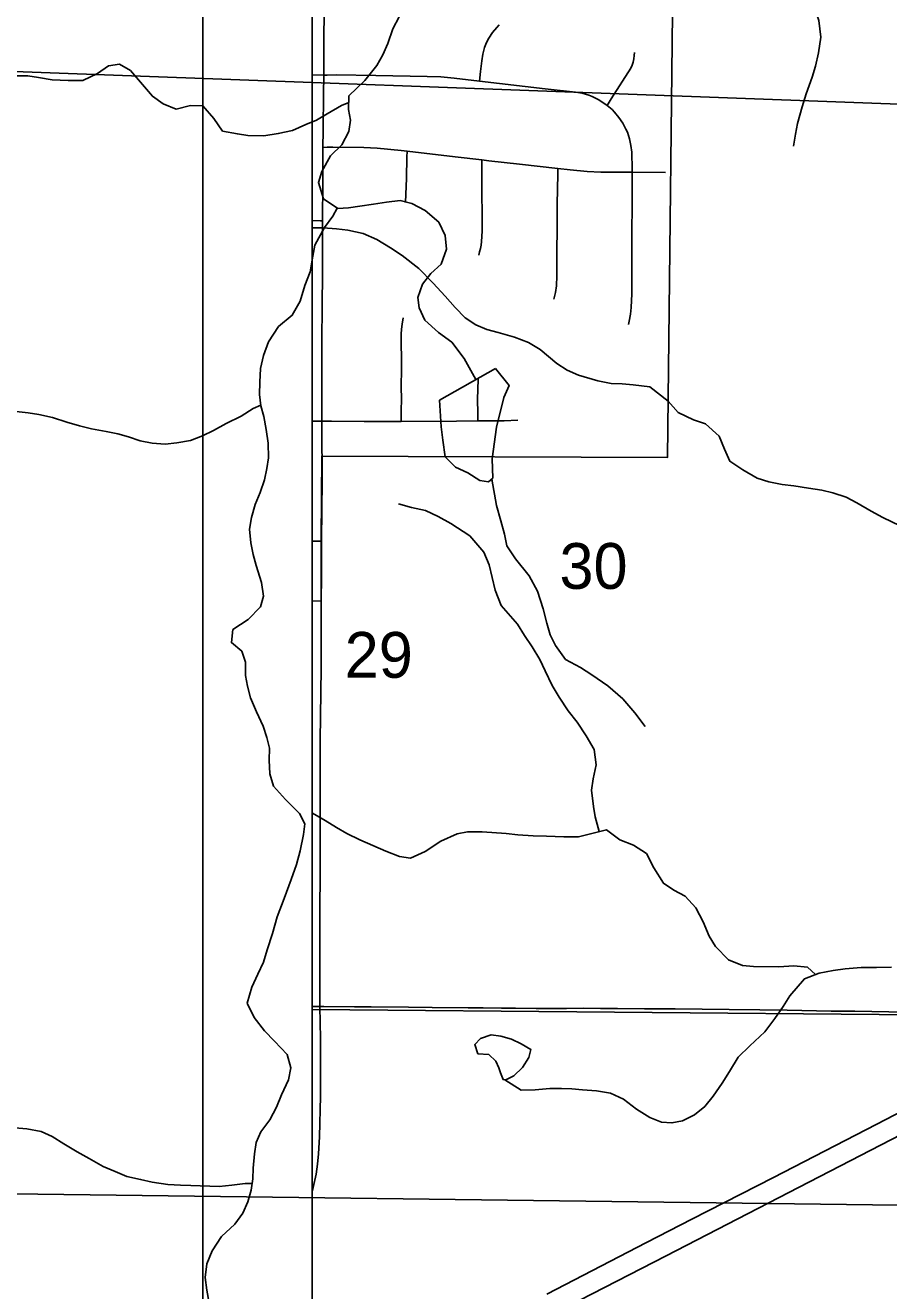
# Model space of a CAD drawing. Extents: x 0 to 34, y 0 to 22.
# Drawn here: x 12.978 to 13.767, y 14.964 to 16.121 of the extents above; entities that cross this region are included whole.
import ezdxf

# ---------------------------------------------------------------- set-up
doc = ezdxf.new("R2010")
doc.units = 0
for name, color, linetype in [('GM_X_City_Street', 7, 'Continuous'), ('GM_X_Corporation', 7, 'Continuous'), ('GM_X_County_Road', 7, 'Continuous'), ('GM_X_Interstate_Route', 7, 'Continuous'), ('GM_X_Minor_Lake', 7, 'Continuous'), ('GM_X_Minor_River', 7, 'Continuous'), ('GM_X_Rail_Line', 7, 'Continuous'), ('GM_X_Section', 7, 'Continuous'), ('GM_X_Section_Text', 7, 'Continuous'), ('GM_X_US_Shield', 7, 'Continuous'), ('SH_Data', 7, 'Continuous')]:
    doc.layers.add(name, color=color, linetype=linetype)

msp = doc.modelspace()

# ---------------------------------------------------------------- linework, layer by layer
at = {"layer": 'GM_X_City_Street'}
for p, q in [((13.2404, 16.0756), (13.2509, 16.0753)), ((13.2404, 15.7589), (13.2491, 15.759)), ((13.2404, 15.6492), (13.2489, 15.6491))]:
    msp.add_line(p, q, dxfattribs=at)
for points in [[(13.3933, 16.0698), (13.3943, 16.0785), (13.3955, 16.0884), (13.3965, 16.0945), (13.398, 16.1006), (13.399, 16.1035), (13.4002, 16.1063), (13.4017, 16.1091), (13.4052, 16.1142), (13.4092, 16.119), (13.4114, 16.1212)], [(13.51, 16.0476), (13.5138, 16.0536), (13.5315, 16.0816), (13.5328, 16.0844), (13.5338, 16.0871), (13.5344, 16.0901), (13.5347, 16.0931), (13.5349, 16.0961)], [(13.2509, 16.0753), (13.2542, 16.0754), (13.2624, 16.0755), (13.2986, 16.0749), (13.3455, 16.0741), (13.3579, 16.0736), (13.3703, 16.0724), (13.3933, 16.0698), (13.4533, 16.0629), (13.481, 16.0598), (13.4872, 16.0587), (13.4932, 16.0569), (13.4962, 16.0558), (13.5018, 16.0529), (13.5071, 16.0497), (13.51, 16.0476), (13.5145, 16.0438), (13.5167, 16.0415), (13.5207, 16.0367), (13.5242, 16.0315), (13.5272, 16.0259), (13.5285, 16.0231), (13.5296, 16.0201), (13.5305, 16.0171), (13.5317, 16.011), (13.5324, 16.0047), (13.5327, 15.9889), (13.5327, 15.9867)], [(13.2502, 16.0092), (13.2542, 16.0093), (13.2594, 16.0093), (13.2875, 16.009), (13.2999, 16.0084), (13.3216, 16.0064), (13.3271, 16.0058), (13.3711, 16.0005), (13.3954, 15.9977), (13.4018, 15.997), (13.4299, 15.9939), (13.4649, 15.9899), (13.4763, 15.9886), (13.4918, 15.9872), (13.5042, 15.9867), (13.5327, 15.9867), (13.5634, 15.9863)], [(13.3258, 15.9587), (13.3267, 15.9811), (13.327, 16.0002), (13.3271, 16.0058)], [(13.3926, 15.9108), (13.3934, 15.9137), (13.3942, 15.9169), (13.3948, 15.9199), (13.3951, 15.9231), (13.3956, 15.9325), (13.3954, 15.9827), (13.3954, 15.9922), (13.3954, 15.9977)], [(13.4614, 15.8703), (13.4628, 15.8764), (13.4636, 15.8826), (13.4641, 15.8919), (13.4643, 15.9573), (13.4648, 15.9847), (13.4649, 15.9899)], [(13.5294, 15.8473), (13.5302, 15.8504), (13.5312, 15.8566), (13.5318, 15.8628), (13.5324, 15.8753), (13.5325, 15.8878), (13.5325, 15.9159), (13.5325, 15.9283), (13.5325, 15.9377), (13.5327, 15.9501), (13.5328, 15.9626), (13.5327, 15.9867)], [(13.2404, 15.9423), (13.2481, 15.9422), (13.2498, 15.9422)], [(13.3218, 15.7586), (13.3218, 15.7647), (13.3218, 15.7677), (13.3219, 15.78), (13.3218, 15.7892), (13.322, 15.8076), (13.3218, 15.8383), (13.322, 15.8429), (13.3226, 15.8475), (13.3237, 15.8535)], [(13.3918, 15.7592), (13.3917, 15.7662), (13.3915, 15.7787), (13.392, 15.7974)], [(13.2491, 15.759), (13.2581, 15.7589), (13.2878, 15.7587), (13.3218, 15.7586), (13.3722, 15.759), (13.3918, 15.7592), (13.3972, 15.7592), (13.416, 15.7592), (13.4285, 15.7597)]]:
    msp.add_lwpolyline(points, dxfattribs=at)
at = {"layer": 'GM_X_Corporation'}
msp.add_lwpolyline([(13.2404, 19.7446), (13.2404, 15.5945), (13.2485, 15.5944), (13.2487, 15.6513), (13.2492, 15.7269), (13.565, 15.7255), (13.5708, 16.2404), (13.5808, 16.7296), (14.5791, 16.7149), (14.5699, 16.2993), (14.5699, 16.2941), (14.627, 16.2968)], dxfattribs=at)
at = {"layer": 'GM_X_County_Road'}
msp.add_line((13.2404, 15.2236), (13.2475, 15.2236), dxfattribs=at)
for points in [[(13.2509, 16.0753), (13.251, 16.1085), (13.2512, 16.1326), (13.2512, 16.1457), (13.251, 16.1612), (13.2513, 16.1885), (13.2516, 16.211), (13.2518, 16.2247), (13.2523, 16.2413)], [(13.2502, 16.0092), (13.2504, 16.0248), (13.2508, 16.0589), (13.2509, 16.0744), (13.2509, 16.0753)], [(13.2498, 15.9422), (13.2498, 15.9443), (13.2501, 15.9753), (13.2502, 16.0032), (13.2502, 16.0092)], [(13.2491, 15.759), (13.2491, 15.7893), (13.2493, 15.8296), (13.2495, 15.8668), (13.2497, 15.8916), (13.2497, 15.9133), (13.2498, 15.9422)], [(13.2494, 15.7247), (13.2492, 15.7336), (13.2491, 15.759)], [(13.2489, 15.6491), (13.2493, 15.6783), (13.2495, 15.7033), (13.2494, 15.7247)], [(13.2487, 15.5922), (13.2488, 15.6189), (13.2489, 15.6491)], [(13.2475, 15.2236), (13.2475, 15.2332), (13.2474, 15.2488), (13.2473, 15.2738), (13.2474, 15.2956), (13.2475, 15.3112), (13.2477, 15.3455), (13.2478, 15.4143), (13.2478, 15.4669), (13.2487, 15.5331), (13.2487, 15.5922)], [(13.2404, 15.0547), (13.2413, 15.058), (13.244, 15.0702), (13.2454, 15.0795), (13.2463, 15.0888), (13.2471, 15.1043), (13.2479, 15.1416), (13.248, 15.1696), (13.2479, 15.1944), (13.2475, 15.2236)], [(13.2475, 15.2236), (13.2511, 15.2236), (13.279, 15.2232), (13.2944, 15.2232), (13.3284, 15.2229), (13.35, 15.2228), (13.383, 15.2225), (13.3967, 15.2223), (13.4133, 15.2222), (13.4261, 15.222), (13.4452, 15.2219), (13.4513, 15.2218), (13.4605, 15.2217), (13.4729, 15.2219), (13.4883, 15.222), (13.5038, 15.2218), (13.5193, 15.2217), (13.5441, 15.2214), (13.572, 15.2214), (13.6216, 15.2209), (13.6496, 15.2206), (13.6744, 15.2201), (13.7148, 15.2194), (13.7365, 15.2192), (13.7831, 15.2185)]]:
    msp.add_lwpolyline(points, dxfattribs=at)
at = {"layer": 'GM_X_Interstate_Route'}
for points in [[(13.2404, 14.8287), (13.3346, 14.8775), (13.4174, 14.9203), (13.5638, 14.9957), (13.8537, 15.1453), (14.0112, 15.2265), (14.0636, 15.2536), (14.0682, 15.2561), (14.0856, 15.2652), (14.1412, 15.2931), (14.2109, 15.3274), (14.267, 15.3543), (14.4477, 15.4375), (14.5127, 15.4672), (14.5664, 15.4917), (14.8291, 15.6122), (14.8912, 15.6408), (14.9562, 15.6704), (15.0269, 15.7029), (15.0724, 15.724)], [(13.4548, 14.9606), (13.5459, 15.0077), (13.5873, 15.0291), (13.662, 15.0672), (13.7558, 15.1158), (13.8552, 15.1671), (13.9712, 15.2268), (14.0043, 15.2439), (14.0457, 15.2654), (14.0685, 15.2771), (14.0927, 15.2895), (14.1398, 15.3134), (14.1954, 15.341), (14.2403, 15.3624), (14.3023, 15.3911), (14.3786, 15.4259), (14.4352, 15.4518), (14.4747, 15.47), (14.5311, 15.496), (14.63, 15.5413)]]:
    msp.add_lwpolyline(points, dxfattribs=at)
at = {"layer": 'GM_X_Minor_Lake'}
for points in [[(13.3568, 15.778), (13.3583, 15.7537), (13.3597, 15.7416), (13.362, 15.7263), (13.3715, 15.7168), (13.3825, 15.7115), (13.3935, 15.7046), (13.4014, 15.7034), (13.4056, 15.7068), (13.4049, 15.7243), (13.4088, 15.7535), (13.4157, 15.7805), (13.4203, 15.7915), (13.4078, 15.8071)], [(13.4078, 15.8071), (13.3568, 15.778)], [(13.4181, 15.1567), (13.4246, 15.1601), (13.4326, 15.1677), (13.4383, 15.1768), (13.4402, 15.1844), (13.4315, 15.1894), (13.4227, 15.1936), (13.4129, 15.1966), (13.4041, 15.1978), (13.3943, 15.1944), (13.3889, 15.1887), (13.3919, 15.1804), (13.4018, 15.1796), (13.4083, 15.1735), (13.4109, 15.1674), (13.4124, 15.1628)], [(13.4124, 15.1628), (13.4149, 15.1567), (13.4166, 15.1564), (13.4181, 15.1567)]]:
    msp.add_lwpolyline(points, dxfattribs=at)
at = {"layer": 'GM_X_Minor_River'}
for points in [[(13.5589, 16.2576), (13.5721, 16.2474), (13.58, 16.2337), (13.5864, 16.2219), (13.5932, 16.2104), (13.6023, 16.1998), (13.6141, 16.191), (13.6247, 16.1856), (13.6387, 16.1799), (13.652, 16.1734), (13.6626, 16.1684), (13.6763, 16.1611), (13.6865, 16.1531), (13.6983, 16.1405), (13.7035, 16.1253), (13.7054, 16.1101), (13.7031, 16.0957), (13.7004, 16.0835), (13.6973, 16.0733), (13.6919, 16.0581), (13.6881, 16.0463), (13.6839, 16.0311), (13.682, 16.0213), (13.6804, 16.0102)], [(13.3198, 16.1286), (13.3141, 16.1175), (13.3095, 16.1043), (13.3049, 16.094), (13.2996, 16.0842), (13.2885, 16.0705), (13.274, 16.0565), (13.2736, 16.044), (13.2755, 16.0341), (13.2739, 16.0238), (13.2674, 16.0117), (13.2572, 16.0015), (13.2491, 15.9871), (13.2461, 15.9772), (13.2506, 15.9623), (13.2639, 15.9532), (13.2737, 15.9539), (13.284, 15.9554), (13.2965, 15.9572), (13.3083, 15.9591), (13.3209, 15.9606), (13.3315, 15.9579), (13.3436, 15.9514), (13.3561, 15.9407), (13.3618, 15.9285), (13.3633, 15.916), (13.3583, 15.9023), (13.3488, 15.894), (13.3412, 15.8841), (13.337, 15.872), (13.3381, 15.8625), (13.3433, 15.8511), (13.3559, 15.84), (13.368, 15.8312), (13.3793, 15.8163), (13.39, 15.797)], [(13.2738, 16.0503), (13.2672, 16.0474), (13.2542, 16.0399), (13.2443, 16.0342), (13.2345, 16.03), (13.2223, 16.0248), (13.2094, 16.0218), (13.1961, 16.0199), (13.1816, 16.02), (13.1721, 16.0215), (13.1585, 16.0242), (13.1505, 16.0357), (13.1403, 16.0471), (13.1293, 16.0475), (13.116, 16.0441), (13.1042, 16.0491), (13.0943, 16.056), (13.0853, 16.0667), (13.0743, 16.0796), (13.0644, 16.0854), (13.0542, 16.0839), (13.0443, 16.0767), (13.0309, 16.0703), (13.0173, 16.0703), (13.0028, 16.0711), (12.9903, 16.0731), (12.9804, 16.0746), (12.9591, 16.0747)], [(13.2632, 15.9536), (13.2593, 15.9464), (13.2517, 15.9361), (13.2429, 15.9198), (13.2409, 15.9096), (13.2386, 15.8955), (13.2336, 15.883), (13.2294, 15.8686), (13.2222, 15.8557), (13.2096, 15.8454), (13.2004, 15.8314), (13.1959, 15.8189), (13.1932, 15.8071), (13.1924, 15.7946), (13.1923, 15.7832), (13.1934, 15.7729), (13.1961, 15.763), (13.1983, 15.7512), (13.2002, 15.7387), (13.2005, 15.7254), (13.199, 15.7155), (13.1967, 15.7053), (13.1928, 15.6935), (13.1882, 15.6825), (13.1848, 15.6707), (13.1832, 15.6601), (13.1843, 15.6475), (13.1866, 15.6369), (13.1892, 15.627), (13.1941, 15.6114), (13.196, 15.5989), (13.1933, 15.589), (13.1819, 15.5776), (13.1678, 15.5682), (13.1666, 15.5564), (13.1761, 15.5484), (13.1795, 15.5385), (13.1794, 15.5263), (13.1813, 15.5165), (13.1839, 15.5058), (13.1896, 15.4929), (13.1956, 15.4799), (13.199, 15.4697), (13.2013, 15.4598), (13.2012, 15.4487), (13.2016, 15.4362), (13.205, 15.4252), (13.216, 15.413), (13.2288, 15.4), (13.2337, 15.3905), (13.2326, 15.381), (13.2295, 15.3658), (13.226, 15.3533), (13.2211, 15.3396), (13.2149, 15.3222), (13.2084, 15.3055), (13.2042, 15.2903), (13.1992, 15.2755), (13.1958, 15.2641), (13.1908, 15.2531), (13.1851, 15.2413), (13.1809, 15.2265), (13.1873, 15.2136), (13.1967, 15.2014), (13.2058, 15.1918), (13.2176, 15.1796), (13.2209, 15.1675), (13.2186, 15.1565), (13.2125, 15.1428), (13.2079, 15.1314), (13.2018, 15.12), (13.1934, 15.109), (13.1892, 15.0992), (13.1877, 15.0889), (13.1865, 15.0756), (13.1861, 15.0661), (13.1845, 15.0555), (13.1815, 15.0449), (13.1769, 15.0346), (13.1696, 15.0244), (13.1574, 15.0134), (13.149, 15.0001), (13.1441, 14.9884), (13.1425, 14.9758), (13.144, 14.9641), (13.1462, 14.9523)], [(13.7778, 15.6632), (13.7618, 15.6708), (13.7512, 15.6766), (13.7383, 15.6842), (13.7285, 15.6895), (13.7163, 15.6934), (13.7061, 15.6957), (13.6939, 15.6976), (13.6806, 15.6996), (13.67, 15.7008), (13.6578, 15.7035), (13.6472, 15.7066), (13.6339, 15.7142), (13.6222, 15.7222), (13.6173, 15.7333), (13.6124, 15.7451), (13.5999, 15.7565), (13.5889, 15.76), (13.5748, 15.7668), (13.5657, 15.7771), (13.5491, 15.7901), (13.5339, 15.7921), (13.5236, 15.7929), (13.5137, 15.7933), (13.5016, 15.7956), (13.4837, 15.801), (13.4735, 15.8056), (13.464, 15.8117), (13.4489, 15.8243), (13.4382, 15.8308), (13.4253, 15.8358), (13.4105, 15.84), (13.3999, 15.8427), (13.39, 15.8469), (13.3802, 15.8534), (13.3711, 15.8629), (13.362, 15.8732), (13.351, 15.885), (13.3378, 15.8984), (13.3226, 15.9102), (13.312, 15.9175), (13.2995, 15.9251), (13.287, 15.9305), (13.2729, 15.9336), (13.2627, 15.9348), (13.2505, 15.9356), (13.2404, 15.9356)], [(13.1934, 15.7736), (13.1866, 15.7703), (13.1756, 15.7635), (13.1619, 15.7567), (13.1501, 15.7503), (13.1402, 15.7454), (13.1291, 15.7412), (13.1166, 15.739), (13.106, 15.7379), (13.0942, 15.7387), (13.0832, 15.741), (13.0725, 15.7445), (13.0627, 15.7472), (13.0521, 15.7495), (13.0388, 15.7518), (13.0278, 15.7545), (13.016, 15.758), (13.0031, 15.7622), (12.9905, 15.7649), (12.9807, 15.7664), (12.9697, 15.7676)], [(13.4045, 15.7059), (13.409, 15.6817), (13.4127, 15.6676), (13.4161, 15.6555), (13.4184, 15.6448), (13.4263, 15.633), (13.4388, 15.6174), (13.4463, 15.6033), (13.4516, 15.5873), (13.455, 15.574), (13.458, 15.5634), (13.4629, 15.5538), (13.472, 15.5409), (13.4857, 15.5336), (13.4959, 15.5268), (13.5107, 15.5168), (13.5243, 15.505), (13.5353, 15.492), (13.5448, 15.4795)], [(13.5027, 15.3835), (13.4989, 15.397), (13.4974, 15.4065), (13.4956, 15.4213), (13.4971, 15.4319), (13.4998, 15.4445), (13.498, 15.4585), (13.4908, 15.4711), (13.4825, 15.4837), (13.4745, 15.494), (13.4662, 15.5065), (13.4598, 15.5172), (13.4533, 15.5305), (13.4484, 15.5408), (13.4416, 15.5526), (13.4344, 15.5629), (13.428, 15.5732), (13.4132, 15.5903), (13.4076, 15.6044), (13.405, 15.6158), (13.402, 15.6276), (13.3974, 15.639), (13.3846, 15.6539), (13.3671, 15.6653), (13.3554, 15.6718), (13.344, 15.6772), (13.3311, 15.6799), (13.3193, 15.6834)], [(13.7003, 15.2528), (13.693, 15.2595), (13.6805, 15.2607), (13.6668, 15.26), (13.6437, 15.2601), (13.6338, 15.2612), (13.6209, 15.2662), (13.6091, 15.2784), (13.6031, 15.2879), (13.5978, 15.3009), (13.591, 15.3138), (13.5812, 15.3245), (13.5709, 15.3299), (13.5614, 15.3363), (13.5527, 15.3504), (13.5459, 15.3634), (13.5342, 15.371), (13.5217, 15.376), (13.5095, 15.3852), (13.4837, 15.3788), (13.4704, 15.3788), (13.4544, 15.3793), (13.4423, 15.3797), (13.4282, 15.3805), (13.4176, 15.3817), (13.3956, 15.3833), (13.3823, 15.3833), (13.3728, 15.3815), (13.3579, 15.3747), (13.3438, 15.3652), (13.3302, 15.3592), (13.3203, 15.3607), (13.3078, 15.3657), (13.2839, 15.3761), (13.2721, 15.3818), (13.2626, 15.3872), (13.2524, 15.3937), (13.2406, 15.4005), (13.2404, 15.4006)], [(13.7698, 15.2596), (13.7561, 15.2593), (13.742, 15.2593), (13.7276, 15.2579), (13.7166, 15.2564), (13.7037, 15.2542), (13.6903, 15.2489), (13.677, 15.2333), (13.6709, 15.2235), (13.6633, 15.2125), (13.6541, 15.2004), (13.6404, 15.1875), (13.6297, 15.1773), (13.6217, 15.164), (13.6152, 15.1534), (13.6068, 15.1416), (13.5992, 15.1322), (13.5897, 15.1246), (13.579, 15.1189), (13.5692, 15.1171), (13.5597, 15.1179), (13.549, 15.1221), (13.5369, 15.1297), (13.5248, 15.1389), (13.513, 15.1442), (13.5001, 15.1466), (13.4876, 15.1474), (13.4777, 15.1482), (13.4682, 15.1486), (13.4576, 15.1486), (13.4443, 15.1475), (13.4314, 15.1472), (13.4164, 15.1564)], [(13.1854, 15.0616), (13.1792, 15.0616), (13.1671, 15.0601), (13.1553, 15.059), (13.1295, 15.0599), (13.12, 15.0603), (13.1086, 15.0607), (13.0941, 15.063), (13.0835, 15.0654), (13.071, 15.0681), (13.0604, 15.0727), (13.0494, 15.0773), (13.0365, 15.0845), (13.0255, 15.0906), (13.0133, 15.0979), (13.0027, 15.1048), (12.9928, 15.1094), (12.9796, 15.1117), (12.9651, 15.1129)]]:
    msp.add_lwpolyline(points, dxfattribs=at)
at = {"layer": 'GM_X_Rail_Line'}
msp.add_lwpolyline([(13.2404, 20.2494), (13.2404, 14.2201)], dxfattribs=at)
at = {"layer": 'GM_X_Section'}
for points in [[(12.8167, 17.0672), (13.8241, 17.0583), (13.8099, 16.0475), (12.8025, 16.0848)], [(12.8025, 16.0848), (13.8099, 16.0475), (13.8003, 15.0417), (12.7986, 15.0544)]]:
    msp.add_lwpolyline(points, close=True, dxfattribs=at)
at = {"layer": 'GM_X_US_Shield'}
for points in [[(13.2404, 16.2423), (13.2404, 15.2209), (14.0694, 15.2136), (14.0733, 16.244)], [(13.2404, 15.2209), (13.2404, 14.2178), (14.0522, 14.2111), (14.0694, 15.2136)]]:
    msp.add_lwpolyline(points, close=True, dxfattribs=at)
at = {"layer": 'SH_Data'}
for p, q in [((13.1404, 21), (13.1404, 14)), ((13.2404, 20.9), (13.2404, 14.1))]:
    msp.add_line(p, q, dxfattribs=at)

# ---------------------------------------------------------------- texts
at = {"layer": 'GM_X_Section_Text'}
for s, p in [('30', (13.4664, 15.6055)), ('29', (13.2701, 15.5242))]:
    msp.add_text(s, height=0.04186, rotation=0, dxfattribs=at).set_placement(p)

doc.saveas('drawing.dxf')
